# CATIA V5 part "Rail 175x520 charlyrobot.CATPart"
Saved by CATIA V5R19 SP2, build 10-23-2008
Part number: Rail 175x520 charlyrobot
Bounding box of the stored display mesh (mm): x 0 to 520, y 0 to 30, z 0 to 175
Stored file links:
  Z:\fausse table rondelle-20220905T211342Z-001\fausse table rondelle\Rail 175x520 charlyrobot.CATPart
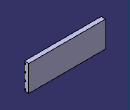
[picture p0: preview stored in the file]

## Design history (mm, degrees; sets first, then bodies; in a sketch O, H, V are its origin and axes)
AxisSystem1: origin (0, 0, 0), X (1, 0, 0), Y (0, 1, 0), Z (0, 0, 1)
Body1 (main body)
  Sketch1 on YZ plane of AxisSystem1, origin (0, 0, 0), H (0, 1, 0), V (0, 0, 1)
    line L1 (0, 0) -> (30, 0)
    line L2 (30, 0) -> (30, 175)
    line L3 (30, 175) -> (0, 175)
    line L4 (0, 175) -> (0, 0)
    distance L4 L2 = 30
    distance L3 L1 = 175
    horizontal: L1 H, L3 H
    vertical: L2 V, L4 V
  Pad1: profile Sketch1, direction (1, 0, 0), length 520
  Sketch2 on YZ plane of AxisSystem1, origin (0, 0, 0), H (0, 1, 0), V (0, 0, 1)
    point P1 (5.125, 12.5)
    line L1 (7.75, 17.75) -> (7.75, 7.25)
    line L2 (7.75, 7.25) -> (2.5, 7.25)
    line L3 (2.5, 7.25) -> (2.5, 9.25)
    line L4 (2.5, 17.75) -> (7.75, 17.75)
    point P6 (1.3125, 12.5)
    construction line L5 (5.125, 9.25) -> (5.125, 15.75)
    line L6 (2.5, 15.75) -> (-2.5, 15.75)
    line L7 (-2.5, 15.75) -> (-2.5, 9.25)
    line L8 (-2.5, 9.25) -> (2.5, 9.25)
    point P7 (5.125, 9.25)
    point P8 (5.125, 15.75)
    reference intersected line E1 through (0, 0) direction (0, 1) from ZX plane of AxisSystem1
    reference intersected line E2 through (0, 0) direction (-1, 0) from XY plane of AxisSystem1
    line L9 (2.5, 15.75) -> (2.5, 17.75)
    length L1 = 10.5
    length L4 = 5.25
    length L7 = 6.5
    distance L3 L7 = 5
    distance L3 E1 = 2.5
    distance P6 E2 = 12.5
    vertical: L1 V, L3 V, L5 V, L7 V
    horizontal: L2 H, L4 H, L6 H, L8 H
    equidistance: L1 L3 P1, L2 L4 P1, L5 L7 P6, L6 L8 P6
    midpoint: L5 P1
    coincidence: L3 L9, P7 L8, P8 L6
  Pocket1: profile Sketch2, direction (-1, 0, 0), through (limit type 3)
  Sketch3 on ZX plane of AxisSystem1, origin (0, 0, 0), H (0, 0, 1), V (1, 0, 0)
    construction line L1 (12.5, 480) -> (12.5, 520)
    point P2 (12.5, 520)
    line L2 (7.4, 480) -> (7.4, 520)
    line L3 (17.6, 520) -> (17.6, 480)
    arc A1 centre (12.5, 520) radius 5.1 from (7.4, 520) to (17.6, 520) cw
    arc A2 centre (12.5, 480) radius 5.1 from (17.6, 480) to (7.4, 480) cw
    reference intersected line E1 through (0, 0) direction (0, 1) from XY plane of AxisSystem1
    reference intersected line E2 (0, 520) -> (200, 520) from end face of Pad1
    distance L1 L2 = 5.1
    distance L1 E1 = 12.5
    length L1 = 40
    vertical: L1 V
    tangency: A1 L2, A2 L2, A1 L3, A2 L3
    coincidence: P2 E2
  Pocket2: profile Sketch3, direction (0, 1, 0), length 5
  RectPattern1: of Pocket1, Pocket2, direction 1 instances 4, spacing 50, along Z axis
